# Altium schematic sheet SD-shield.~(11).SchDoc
size A; SheetNumber: 1; SheetTotal: 1
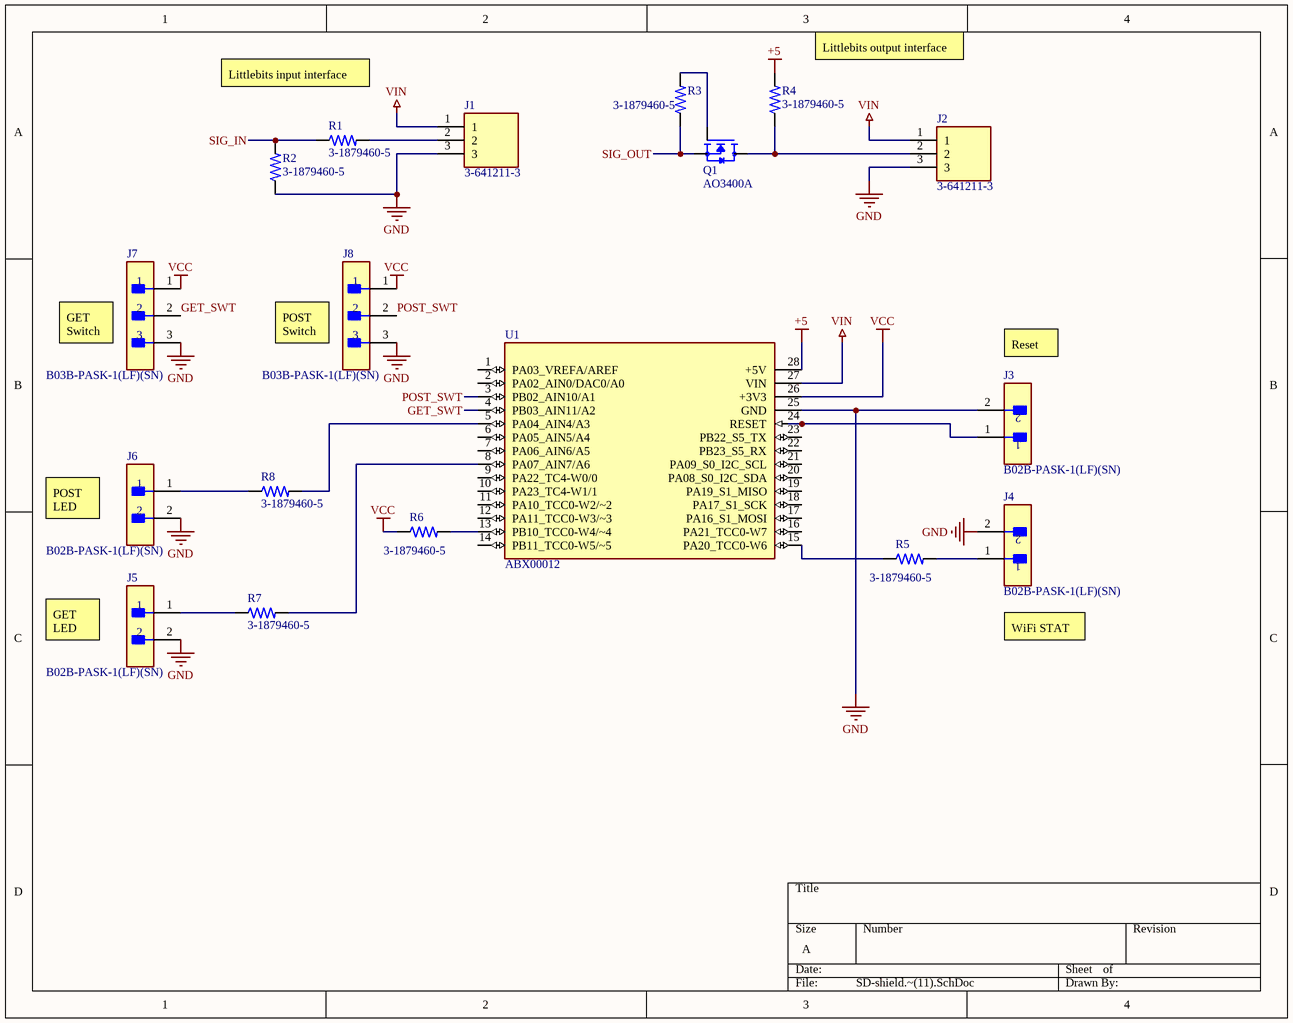
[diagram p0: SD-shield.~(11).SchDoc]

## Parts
J1  3-641211-3  [TE_3-641211-3]
J2  3-641211-3  [TE_3-641211-3]
J3  B02B-PASK-1(LF)(SN)  [FP-B02B-PASK-1_LF_SN-MFG]
J4  B02B-PASK-1(LF)(SN)  [FP-B02B-PASK-1_LF_SN-MFG]
J5  B02B-PASK-1(LF)(SN)  [FP-B02B-PASK-1_LF_SN-MFG]
J6  B02B-PASK-1(LF)(SN)  [FP-B02B-PASK-1_LF_SN-MFG]
J7  B03B-PASK-1(LF)(SN)  [FP-B03B-PASK-1_LF_SN-MFG]
J8  B03B-PASK-1(LF)(SN)  [FP-B03B-PASK-1_LF_SN-MFG]
Q1  AO3400A  [SOT95P280X125-3N]
R1  3-1879460-5  [RESC1608X50N]
R2  3-1879460-5  [RESC1608X50N]
R3  3-1879460-5  [RESC1608X50N]
R4  3-1879460-5  [RESC1608X50N]
R5  3-1879460-5  [RESC1608X50N]
R6  3-1879460-5  [RESC1608X50N]
R7  3-1879460-5  [RESC1608X50N]
R8  3-1879460-5  [RESC1608X50N]
U1  ABX00012  [ARDUINO_ABX00012]

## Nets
+5: R4.2 U1.28(+5V)
GND: J1.3 J2.3 J3.2 J4.2 J5.2 J6.2 J7.3 J8.3 R2.1 U1.25(GND)
VCC: J7.1 J8.1 R6.1 U1.26(+3V3)
VIN: J1.1 J2.1 U1.27(VIN)
GET_SWT: J7.2 U1.4(PB03_AIN11/A2)
POST_SWT: J8.2 U1.3(PB02_AIN10/A1)
SIG_IN: R1.1 R2.2
SIG_OUT: Q1.2(S) R3.1
NetJ1_2: J1.2 R1.2
NetJ2_2: J2.2 Q1.3(D) R4.1
NetJ3_1: J3.1 U1.24(RESET)
NetJ4_1: J4.1 R5.2
NetJ5_1: J5.1 R7.1
NetJ6_1: J6.1 R8.1
NetQ1_1: Q1.1(G) R3.2
NetR5_1: R5.1 U1.15(PA20_TCC0-W6)
NetR6_2: R6.2 U1.13(PB10_TCC0-W4/~4)
NetR7_2: R7.2 U1.8(PA07_AIN7/A6)
NetR8_2: R8.2 U1.5(PA04_AIN4/A3)

Not connected (* = marked no-connect by the designer): U1 1(PA03_VREFA/AREF) 2(PA02_AIN0/DAC0/A0) 6(PA05_AIN5/A4) 7(PA06_AIN6/A5) 9(PA22_TC4-W0/0) 10(PA23_TC4-W1/1) 11(PA10_TCC0-W2/~2) 12(PA11_TCC0-W3/~3) 14(PB11_TCC0-W5/~5) 16(PA21_TCC0-W7) 17(PA16_S1_MOSI) 18(PA17_S1_SCK) 19(PA19_S1_MISO) 20(PA08_S0_I2C_SDA) 21(PA09_S0_I2C_SCL) 22(PB23_S5_RX) 23(PB22_S5_TX)

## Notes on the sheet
- Littlebits input interface
- (near R4) Littlebits output interface
- (near J7) GET Switch
- (near J8) POST Switch
- Reset
- POST LED
- GET LED
- WiFi STAT

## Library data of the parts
J3-J6 = CMP-17439-000415-1: CONN HEADER VERT 2POS 2MM; Number of Contacts: 2; Current Rating: 3A; Insulation Resistance: 1GR; Mated Stacking Heights: 14.9mm; Voltage Rating: 250V; Gender: Male
J7 J8 = CMP-17439-000193-1: CONN HEADER VERT 3POS 2MM; Voltage Rating: 250V; Current Rating: 3A; Mated Stacking Heights: 14.9mm; Number of Positions: 3
Q1 = AO3400A: Trans MOSFET N-CH 30V 5.7A 3-Pin SOT-23
R1-R8 = 3-1879460-5: RES 0.27 OHM 1% 1/10W 0603; Resistance: 27; MF: TE Connectivity; Power_Rating: .1 W
U1 = ABX00012: MKR footprint/pins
